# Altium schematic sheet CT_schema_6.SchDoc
size 422 x 246 mm
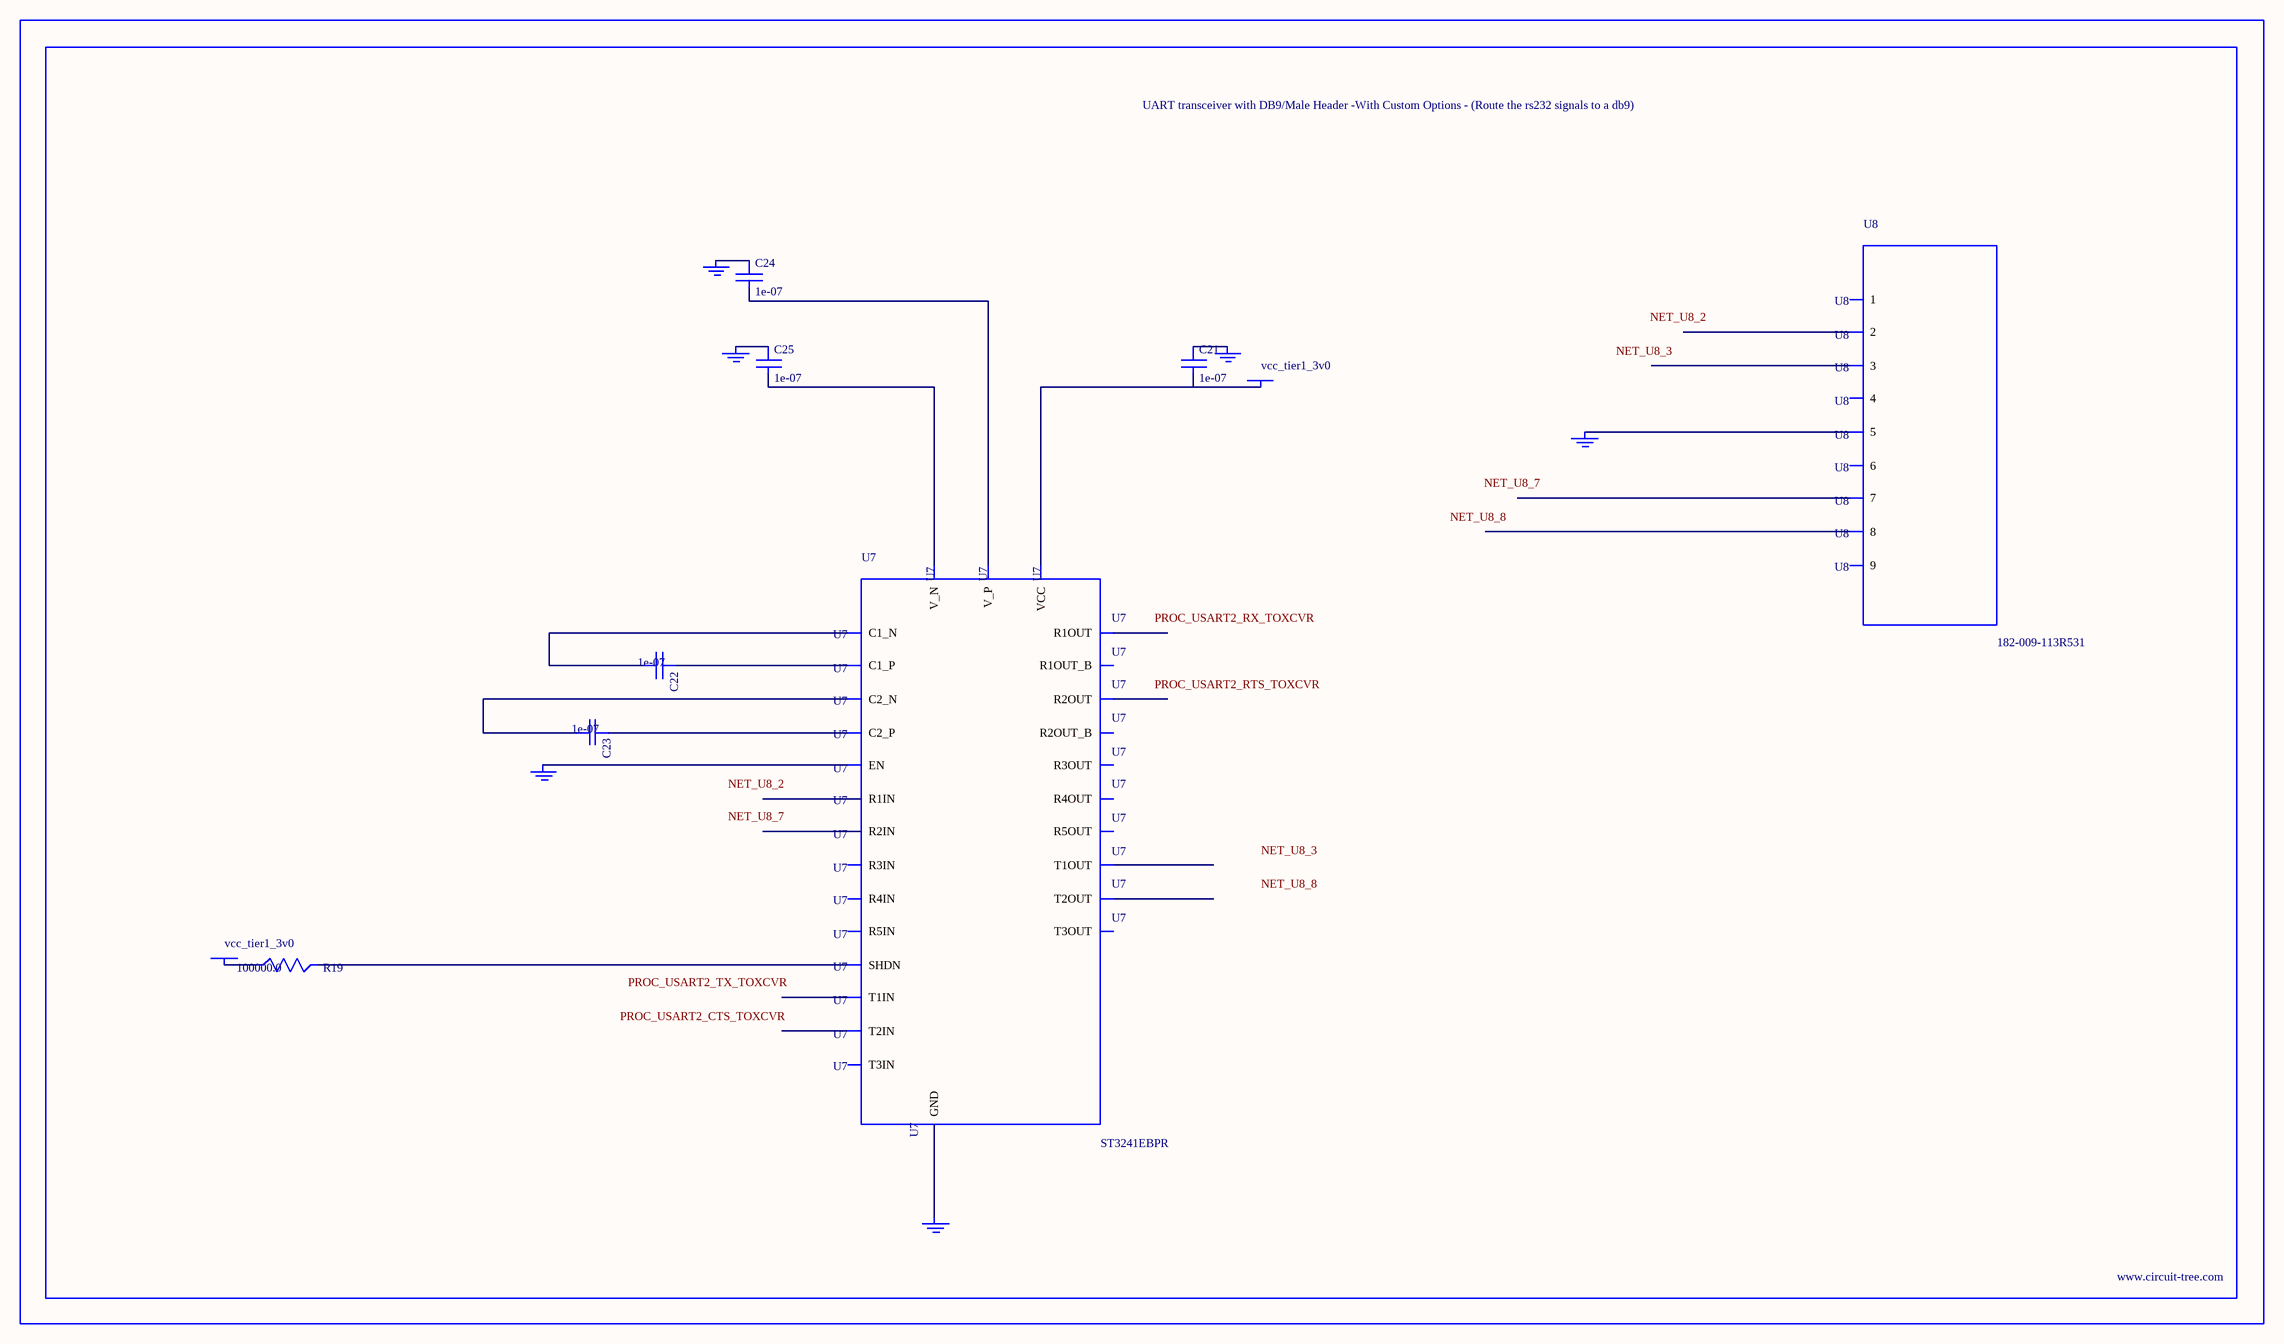
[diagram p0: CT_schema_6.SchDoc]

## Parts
BORDER5  (no value)
C21  1e-07  [C0402]
C22  1e-07  [C0402]
C23  1e-07  [C0402]
C24  1e-07  [C0402]
C25  1e-07  [C0402]
GND_INSTANCE_5_0  (no value)
GND_INSTANCE_5_1  (no value)
GND_INSTANCE_5_2  (no value)
GND_INSTANCE_5_3  (no value)
GND_INSTANCE_5_4  (no value)
GND_INSTANCE_5_5  (no value)
POWER_INSTANCE_5_0  vcc_tier1_3v0
POWER_INSTANCE_5_1  vcc_tier1_3v0
R19  100000.0  [R0603]
U7  ST3241EBPR  [SSOP-28]
U8  182-009-113R531  [182-009-MALE]

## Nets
NetC21_1: C21.1 GND_INSTANCE_5_2.0(GND)
NetC21_2: C21.2 POWER_INSTANCE_5_1.0(PWR) U7.26(VCC)
NetC22_1: C22.1 U7.28(C1_P)
NetC22_2: C22.2 U7.24(C1_N)
NetC23_1: C23.1 U7.1(C2_P)
NetC23_2: C23.2 U7.2(C2_N)
NetC24_1: C24.1 GND_INSTANCE_5_3.0(GND)
NetC24_2: C24.2 U7.27(V_P)
NetC25_1: C25.1 GND_INSTANCE_5_0.0(GND)
NetC25_2: C25.2 U7.3(V_N)
NetGND_INSTANCE_5_1_0: GND_INSTANCE_5_1.0(GND) U7.23(EN)
NetGND_INSTANCE_5_4_0: GND_INSTANCE_5_4.0(GND) U7.25(GND)
NetGND_INSTANCE_5_5_0: GND_INSTANCE_5_5.0(GND) U8.5
NetPOWER_INSTANCE_5_0_0: POWER_INSTANCE_5_0.0(PWR) R19.1
NetR19_2: R19.2 U7.22(SHDN)

Not connected (* = marked no-connect by the designer): U7 4(R1IN) 5(R2IN) 6(R3IN) 7(R4IN) 8(R5IN) 9(T1OUT) 10(T2OUT) 11(T3OUT) 12(T3IN) 13(T2IN) 14(T1IN) 15(R5OUT) 16(R4OUT) 17(R3OUT) 18(R2OUT) 19(R1OUT) 20(R2OUT_B) 21(R1OUT_B); U8 1 2 3 4 6 7 8 9

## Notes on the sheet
- Labels drawn without touching a wire or pin: NET_U8_2, NET_U8_3, NET_U8_7, NET_U8_8, PROC_USART2_CTS_TOXCVR, PROC_USART2_RTS_TOXCVR, PROC_USART2_RX_TOXCVR, PROC_USART2_TX_TOXCVR

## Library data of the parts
BORDER5 = BORDER_PAGE5
C21-C25 = C0402C104K3RACTU
GND_INSTANCE_5_0-GND_INSTANCE_5_5 = GND
POWER_INSTANCE_5_0 POWER_INSTANCE_5_1 = PWR
R19 = RC0603JR-07100KL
